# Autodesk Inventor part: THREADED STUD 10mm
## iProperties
Created: 2007-03
Part Number: THREADED STUD 10mm
Document SubType Name: Modeling
Designer: Andy Moles
Material: Steel
Mass: 52.5811 g
Surface Area: 26.5957 cm^2
Volume: 6.69823 cm^3
Density: 7.85 g/cm^3
Author: Andy Moles
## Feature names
1. Revolution1
2. Extrusion1
3. Extrusion2
4. Extrusion3
5. Chamfer1
